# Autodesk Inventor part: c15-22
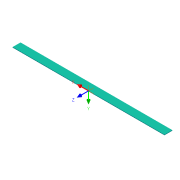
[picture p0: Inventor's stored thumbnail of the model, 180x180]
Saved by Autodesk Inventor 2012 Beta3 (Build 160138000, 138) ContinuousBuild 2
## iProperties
Created: 2011-02
Part Number: c15-22
Material: Default
Document SubType Name: Modeling
Designer: Beta-8540w
Density: 1 g/cm^3
Author: Beta-8540w
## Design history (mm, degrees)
sketch "Sketch1"
  geometry: L1 (-152.4, 7.938)-(152.4, 7.938); L2 (152.4, 7.938)-(152.4, -7.938); L3 (152.4, -7.938)-(-152.4, -7.938); L4 (-152.4, -7.938)-(-152.4, 7.938); 3 further points
  constraints: 8 end point, 2 midpoint, 2 parallel, 1 horizontal, 1 horizontal alignment, 1 perpendicular, 1 vertical alignment
  dimensions: "length" = 304.8 distance of L1.start L1.end; "d1" = 15.875 distance of L1.end L2.end
extrude "Extrusion1" new body sketch "Sketch1" taper "d3" = 0 deg; distance "thickness" = 1
body "Solid1"
other parameters: "d4" = 0, "d5" = 0, "d6" = 0, "d7" = 0, "d8" = 0, "d9" = 0
